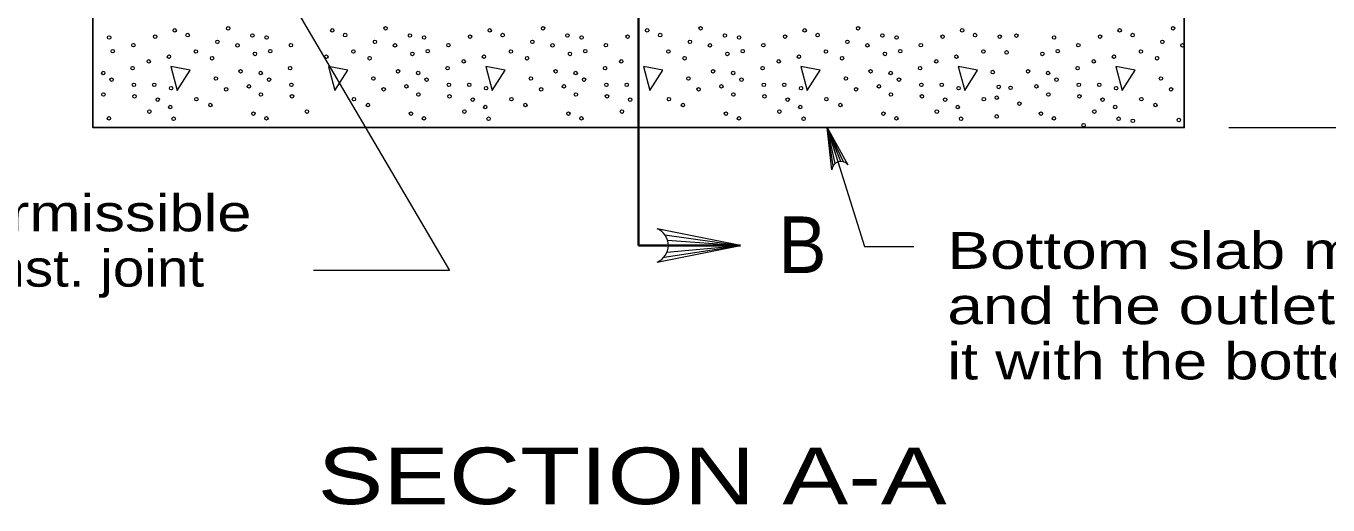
# Model space of a CAD drawing. Extents: x -410.5 to -376.5, y 1617.6 to 1661.6.
# Drawn here: x -405.64 to -400.12, y 1650.53 to 1652.56 of the extents above; entities that cross this region are included whole.
import ezdxf

# ---------------------------------------------------------------- set-up
doc = ezdxf.new("R2010")
doc.units = 0
doc.header["$LTSCALE"] = 0.062
doc.layers.add('1', color=7, linetype='Continuous', lineweight=13)

msp = doc.modelspace()

# ---------------------------------------------------------------- linework, layer by layer
at = {"layer": '1', "lineweight": 35}
for q in [(-403.04708, 1655.833), (-402.61442, 1651.63225)]:
    msp.add_line((-403.04708, 1651.63225), q, dxfattribs=at)
at = {"layer": '1'}
for p, q in [((-402.20133, 1651.98608), (-402.24808, 1652.13192)), ((-402.21417, 1651.979), (-402.24808, 1652.13192)), ((-402.22225, 1651.97), (-402.24808, 1652.13192)), ((-402.19008, 1651.988), (-402.24808, 1652.13192)), ((-402.17783, 1651.98617), (-402.24808, 1652.13192)), ((-400.54525, 1652.13192), (-395.02575, 1652.13192)), ((-402.93875, 1651.58267), (-402.61442, 1651.63225)), ((-402.93492, 1651.67708), (-402.61442, 1651.63225)), ((-402.92642, 1651.60342), (-402.61442, 1651.63225)), ((-402.92408, 1651.65492), (-402.61442, 1651.63225)), ((-402.92075, 1651.63225), (-402.61442, 1651.63225))]:
    msp.add_line(p, q, dxfattribs=at)
at = {"layer": '1', "lineweight": 25}
msp.add_lwpolyline([(-405.35992, 1654.77925), (-405.35992, 1652.13192), (-400.73433, 1652.13192), (-400.73433, 1653.76683), (-401.67833, 1653.76683), (-401.67833, 1653.71308)], dxfattribs=at)
at = {"layer": '1'}
for points in [[(-404.67042, 1652.92708), (-403.8485, 1651.52508), (-404.42508, 1651.52508)], [(-402.22783, 1651.95258), (-402.24808, 1652.13192), (-402.16033, 1651.97417)], [(-402.24808, 1652.13192), (-402.08908, 1651.62767), (-401.88033, 1651.62767)], [(-402.96842, 1651.56142), (-402.61442, 1651.63225), (-402.96842, 1651.703)]]:
    msp.add_lwpolyline(points, dxfattribs=at)
for points in [[(-405.02917, 1652.39117), (-405.00225, 1652.28883), (-404.94733, 1652.37525)], [(-404.36175, 1652.39117), (-404.33475, 1652.28883), (-404.27975, 1652.37525)], [(-403.69425, 1652.39117), (-403.66725, 1652.28883), (-403.61225, 1652.37525)], [(-403.02667, 1652.39117), (-402.99975, 1652.28883), (-402.94475, 1652.37525)], [(-402.35917, 1652.39117), (-402.33217, 1652.28883), (-402.27725, 1652.37525)], [(-401.69167, 1652.39117), (-401.66467, 1652.28883), (-401.60975, 1652.37525)], [(-401.02417, 1652.39117), (-400.99725, 1652.28883), (-400.94225, 1652.37525)]]:
    msp.add_lwpolyline(points, close=True, dxfattribs=at)
for centre, radius, start, end in [((-402.18967, 1651.94978), 0.0382, 39.85416, 175.68029), ((-402.99703, 1651.6323), 0.0764, 292.08605, 67.91218)]:
    msp.add_arc(centre, radius, start, end, dxfattribs=at)
for centre, major_axis in [((-405.29083, 1652.5142), (0, -0.00756)), ((-405.09586, 1652.51779), (0, -0.00756)), ((-405.01292, 1652.54447), (0, -0.00756)), ((-404.95797, 1652.52445), (0, -0.00756)), ((-404.78647, 1652.55336), (0, 0.00756)), ((-404.68368, 1652.52286), (0, 0.00756)), ((-404.62332, 1652.5142), (0, -0.00756)), ((-404.34542, 1652.54447), (0, -0.00756)), ((-404.29046, 1652.52445), (0, -0.00756)), ((-404.11896, 1652.55336), (0, 0.00756)), ((-404.01617, 1652.52286), (0, 0.00756)), ((-403.95581, 1652.5142), (0, -0.00756)), ((-403.76085, 1652.51779), (0, -0.00756)), ((-403.67791, 1652.54447), (0, -0.00756)), ((-403.62295, 1652.52445), (0, -0.00756)), ((-403.45146, 1652.55336), (0, 0.00756)), ((-403.34866, 1652.52286), (0, 0.00756)), ((-403.2883, 1652.5142), (0, -0.00756)), ((-403.09334, 1652.51779), (0, -0.00756)), ((-403.0104, 1652.54447), (0, -0.00756)), ((-402.95544, 1652.52445), (0, -0.00756)), ((-402.78395, 1652.55336), (0, 0.00756)), ((-402.68115, 1652.52286), (0, 0.00756)), ((-402.6208, 1652.5142), (0, -0.00756)), ((-402.42583, 1652.51779), (0, -0.00756)), ((-402.34289, 1652.54447), (0, -0.00756)), ((-402.28793, 1652.52445), (0, -0.00756)), ((-402.11644, 1652.55336), (0, 0.00756)), ((-402.01364, 1652.52286), (0, 0.00756)), ((-401.95329, 1652.5142), (0, -0.00756)), ((-401.75832, 1652.51779), (0, -0.00756)), ((-401.67538, 1652.54447), (0, -0.00756)), ((-401.62042, 1652.52445), (0, -0.00756)), ((-401.5163, 1652.51779), (0, -0.00756)), ((-401.44537, 1652.52197), (0, -0.00756)), ((-401.28578, 1652.5142), (0, -0.00756)), ((-401.09081, 1652.51779), (0, -0.00756)), ((-401.00787, 1652.54447), (0, -0.00756)), ((-400.95292, 1652.52445), (0, -0.00756)), ((-400.78142, 1652.55336), (0, 0.00756)), ((-405.27553, 1652.45608), (0, -0.00756)), ((-405.18809, 1652.48175), (0, -0.00756)), ((-404.92287, 1652.45478), (0, 0.00756)), ((-404.83181, 1652.49583), (0, 0.00756)), ((-404.74681, 1652.48087), (0, 0.00756)), ((-404.60802, 1652.45608), (0, -0.00756)), ((-404.52058, 1652.48175), (0, -0.00756)), ((-404.25536, 1652.45478), (0, 0.00756)), ((-404.1643, 1652.49583), (0, 0.00756)), ((-404.0793, 1652.48087), (0, 0.00756)), ((-403.94052, 1652.45608), (0, -0.00756)), ((-403.85307, 1652.48175), (0, -0.00756)), ((-403.58785, 1652.45478), (0, 0.00756)), ((-403.49679, 1652.49583), (0, 0.00756)), ((-403.41179, 1652.48087), (0, 0.00756)), ((-403.27301, 1652.45608), (0, -0.00756)), ((-403.18556, 1652.48175), (0, -0.00756)), ((-402.92034, 1652.45478), (0, 0.00756)), ((-402.82928, 1652.49583), (0, 0.00756)), ((-402.74429, 1652.48087), (0, 0.00756)), ((-402.6055, 1652.45608), (0, -0.00756)), ((-402.51806, 1652.48175), (0, -0.00756)), ((-402.25283, 1652.45478), (0, 0.00756)), ((-402.16177, 1652.49583), (0, 0.00756)), ((-402.07678, 1652.48087), (0, 0.00756)), ((-401.93799, 1652.45608), (0, -0.00756)), ((-401.85055, 1652.48175), (0, -0.00756)), ((-401.58532, 1652.45478), (0, 0.00756)), ((-401.48709, 1652.45093), (0, -0.00756)), ((-401.27048, 1652.45608), (0, -0.00756)), ((-401.18304, 1652.48175), (0, -0.00756)), ((-400.91782, 1652.45478), (0, 0.00756)), ((-400.82676, 1652.49583), (0, 0.00756)), ((-400.74176, 1652.48087), (0, 0.00756)), ((-405.12295, 1652.41279), (0, -0.00756)), ((-405.03729, 1652.43281), (0, -0.00756)), ((-404.85434, 1652.42616), (0, 0.00756)), ((-404.67294, 1652.44459), (0, 0.00756)), ((-404.36978, 1652.43281), (0, -0.00756)), ((-404.18683, 1652.42616), (0, 0.00756)), ((-404.00543, 1652.44459), (0, 0.00756)), ((-403.78793, 1652.41279), (0, -0.00756)), ((-403.70227, 1652.43281), (0, -0.00756)), ((-403.51932, 1652.42616), (0, 0.00756)), ((-403.33792, 1652.44459), (0, 0.00756)), ((-403.12043, 1652.41279), (0, -0.00756)), ((-402.85181, 1652.42616), (0, 0.00756)), ((-402.67041, 1652.44459), (0, 0.00756)), ((-402.45292, 1652.41279), (0, -0.00756)), ((-402.36725, 1652.43281), (0, -0.00756)), ((-402.1843, 1652.42616), (0, 0.00756)), ((-402.00291, 1652.44459), (0, 0.00756)), ((-401.78541, 1652.41279), (0, -0.00756)), ((-401.69975, 1652.43281), (0, -0.00756)), ((-401.3354, 1652.44459), (0, 0.00756)), ((-401.1179, 1652.41279), (0, -0.00756)), ((-401.03224, 1652.43281), (0, -0.00756)), ((-400.84928, 1652.42616), (0, 0.00756)), ((-405.31603, 1652.3635), (0, 0.00756)), ((-405.19137, 1652.38417), (0, -0.00756)), ((-404.83809, 1652.34029), (0, 0.00756)), ((-404.73357, 1652.37086), (0, 0.00756)), ((-404.64852, 1652.3635), (0, 0.00756)), ((-404.52386, 1652.38417), (0, -0.00756)), ((-404.17058, 1652.34029), (0, 0.00756)), ((-404.06606, 1652.37086), (0, 0.00756)), ((-403.98101, 1652.3635), (0, 0.00756)), ((-403.85635, 1652.38417), (0, -0.00756)), ((-403.50308, 1652.34029), (0, 0.00756)), ((-403.39856, 1652.37086), (0, 0.00756)), ((-403.3135, 1652.3635), (0, 0.00756)), ((-403.18885, 1652.38417), (0, -0.00756)), ((-402.83557, 1652.34029), (0, 0.00756)), ((-402.73105, 1652.37086), (0, 0.00756)), ((-402.64599, 1652.3635), (0, 0.00756)), ((-402.52134, 1652.38417), (0, -0.00756)), ((-402.16806, 1652.34029), (0, 0.00756)), ((-402.06354, 1652.37086), (0, 0.00756)), ((-401.97849, 1652.3635), (0, 0.00756)), ((-401.85383, 1652.38417), (0, -0.00756)), ((-401.54551, 1652.36735), (0, -0.00756)), ((-401.39603, 1652.37086), (0, 0.00756)), ((-401.31098, 1652.3635), (0, 0.00756)), ((-401.18632, 1652.38417), (0, -0.00756)), ((-400.83304, 1652.34029), (0, 0.00756)), ((-405.2806, 1652.33552), (0, -0.00756)), ((-405.18598, 1652.31356), (0, -0.00756)), ((-405.09942, 1652.31356), (0, 0.00756)), ((-405.02828, 1652.29925), (0, -0.00756)), ((-404.79482, 1652.29448), (0, 0.00756)), ((-404.69842, 1652.3069), (0, 0.00756)), ((-404.61309, 1652.33552), (0, -0.00756)), ((-404.51847, 1652.31356), (0, -0.00756)), ((-404.12731, 1652.29448), (0, 0.00756)), ((-404.03091, 1652.3069), (0, 0.00756)), ((-403.94558, 1652.33552), (0, -0.00756)), ((-403.85096, 1652.31356), (0, -0.00756)), ((-403.76441, 1652.31356), (0, 0.00756)), ((-403.69326, 1652.29925), (0, -0.00756)), ((-403.4598, 1652.29448), (0, 0.00756)), ((-403.3634, 1652.3069), (0, 0.00756)), ((-403.27807, 1652.33552), (0, -0.00756)), ((-403.18345, 1652.31356), (0, -0.00756)), ((-403.0969, 1652.31356), (0, 0.00756)), ((-402.79229, 1652.29448), (0, 0.00756)), ((-402.69589, 1652.3069), (0, 0.00756)), ((-402.61056, 1652.33552), (0, -0.00756)), ((-402.51594, 1652.31356), (0, -0.00756)), ((-402.42939, 1652.31356), (0, 0.00756)), ((-402.35824, 1652.29925), (0, -0.00756)), ((-402.12478, 1652.29448), (0, 0.00756)), ((-402.02838, 1652.3069), (0, 0.00756)), ((-401.94305, 1652.33552), (0, -0.00756)), ((-401.84843, 1652.31356), (0, -0.00756)), ((-401.76188, 1652.31356), (0, 0.00756)), ((-401.69073, 1652.29925), (0, -0.00756)), ((-401.52048, 1652.30466), (0, -0.00756)), ((-401.4704, 1652.30048), (0, -0.00756)), ((-401.36087, 1652.3069), (0, 0.00756)), ((-401.27554, 1652.33552), (0, -0.00756)), ((-401.18092, 1652.31356), (0, -0.00756)), ((-401.09437, 1652.31356), (0, 0.00756)), ((-401.02323, 1652.29925), (0, -0.00756)), ((-400.78976, 1652.29448), (0, 0.00756)), ((-405.31514, 1652.27222), (0, -0.00756)), ((-405.18331, 1652.26491), (0, -0.00756)), ((-405.08502, 1652.2506), (0, 0.00756)), ((-404.92103, 1652.25249), (0, -0.00756)), ((-404.86157, 1652.22769), (0, -0.00756)), ((-404.64763, 1652.27222), (0, -0.00756)), ((-404.5158, 1652.26491), (0, -0.00756)), ((-404.25352, 1652.25249), (0, -0.00756)), ((-404.19406, 1652.22769), (0, -0.00756)), ((-403.98012, 1652.27222), (0, -0.00756)), ((-403.84829, 1652.26491), (0, -0.00756)), ((-403.75, 1652.2506), (0, 0.00756)), ((-403.58601, 1652.25249), (0, -0.00756)), ((-403.52655, 1652.22769), (0, -0.00756)), ((-403.31261, 1652.27222), (0, -0.00756)), ((-403.18078, 1652.26491), (0, -0.00756)), ((-403.08249, 1652.2506), (0, 0.00756)), ((-402.91851, 1652.25249), (0, -0.00756)), ((-402.85904, 1652.22769), (0, -0.00756)), ((-402.6451, 1652.27222), (0, -0.00756)), ((-402.51327, 1652.26491), (0, -0.00756)), ((-402.41498, 1652.2506), (0, 0.00756)), ((-402.251, 1652.25249), (0, -0.00756)), ((-402.19153, 1652.22769), (0, -0.00756)), ((-401.9776, 1652.27222), (0, -0.00756)), ((-401.84576, 1652.26491), (0, -0.00756)), ((-401.74747, 1652.2506), (0, 0.00756)), ((-401.58349, 1652.25249), (0, -0.00756)), ((-401.52882, 1652.25869), (0, -0.00756)), ((-401.43285, 1652.23362), (0, -0.00756)), ((-401.31009, 1652.27222), (0, -0.00756)), ((-401.17825, 1652.26491), (0, -0.00756)), ((-401.07996, 1652.2506), (0, 0.00756)), ((-400.91598, 1652.25249), (0, -0.00756)), ((-400.85652, 1652.22769), (0, -0.00756)), ((-405.12023, 1652.20001), (0, 0.00756)), ((-405.03189, 1652.2191), (0, 0.00756)), ((-404.67917, 1652.19112), (0, -0.00756)), ((-404.45272, 1652.20001), (0, 0.00756)), ((-404.01166, 1652.19112), (0, -0.00756)), ((-403.78521, 1652.20001), (0, 0.00756)), ((-403.69688, 1652.2191), (0, 0.00756)), ((-403.34415, 1652.19112), (0, -0.00756)), ((-403.1177, 1652.20001), (0, 0.00756)), ((-402.67664, 1652.19112), (0, -0.00756)), ((-402.45019, 1652.20001), (0, 0.00756)), ((-402.36186, 1652.2191), (0, 0.00756)), ((-402.00914, 1652.19112), (0, -0.00756)), ((-401.78268, 1652.20001), (0, 0.00756)), ((-401.69435, 1652.2191), (0, 0.00756)), ((-401.52882, 1652.17929), (0, -0.00756)), ((-401.34163, 1652.19112), (0, -0.00756)), ((-401.11518, 1652.20001), (0, 0.00756)), ((-401.02684, 1652.2191), (0, 0.00756)), ((-405.29172, 1652.1711), (0, -0.00756)), ((-405.01743, 1652.16951), (0, 0.00756)), ((-404.62421, 1652.1711), (0, -0.00756)), ((-403.9567, 1652.1711), (0, -0.00756)), ((-403.68241, 1652.16951), (0, 0.00756)), ((-403.28919, 1652.1711), (0, -0.00756)), ((-402.62169, 1652.1711), (0, -0.00756)), ((-402.3474, 1652.16951), (0, 0.00756)), ((-401.95418, 1652.1711), (0, -0.00756)), ((-401.67989, 1652.16951), (0, 0.00756)), ((-401.28667, 1652.1711), (0, -0.00756)), ((-401.16051, 1652.14248), (0, 0.00756)), ((-401.01238, 1652.16951), (0, 0.00756)), ((-400.95203, 1652.16085), (0, -0.00756)), ((-400.75706, 1652.16444), (0, -0.00756))]:
    msp.add_ellipse(centre, major_axis=major_axis, ratio=0.944543, dxfattribs=at)

# ---------------------------------------------------------------- texts
for s, height, width, p in [('Permissible', 0.156, 1.25, (-406.035, 1651.69192)), ('B', 0.24, 0.95, (-402.45375, 1651.51508)), ('Bottom slab may be precast separately', 0.156, 1.3, (-401.73825, 1651.53283)), ('const. joint', 0.156, 1.15, (-406.035, 1651.45725)), ('and the outlet pipe placed on top of', 0.156, 1.3, (-401.73825, 1651.29817)), ('it with the bottom shaped to drain.', 0.156, 1.25, (-401.73825, 1651.0635)), ('SECTION A-A', 0.24, 1.3, (-404.40717, 1650.5345))]:
    msp.add_text(s, height=height, dxfattribs=dict(at, width=width)).set_placement(p)

doc.saveas('drawing.dxf')
